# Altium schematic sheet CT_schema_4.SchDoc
size 398 x 262 mm
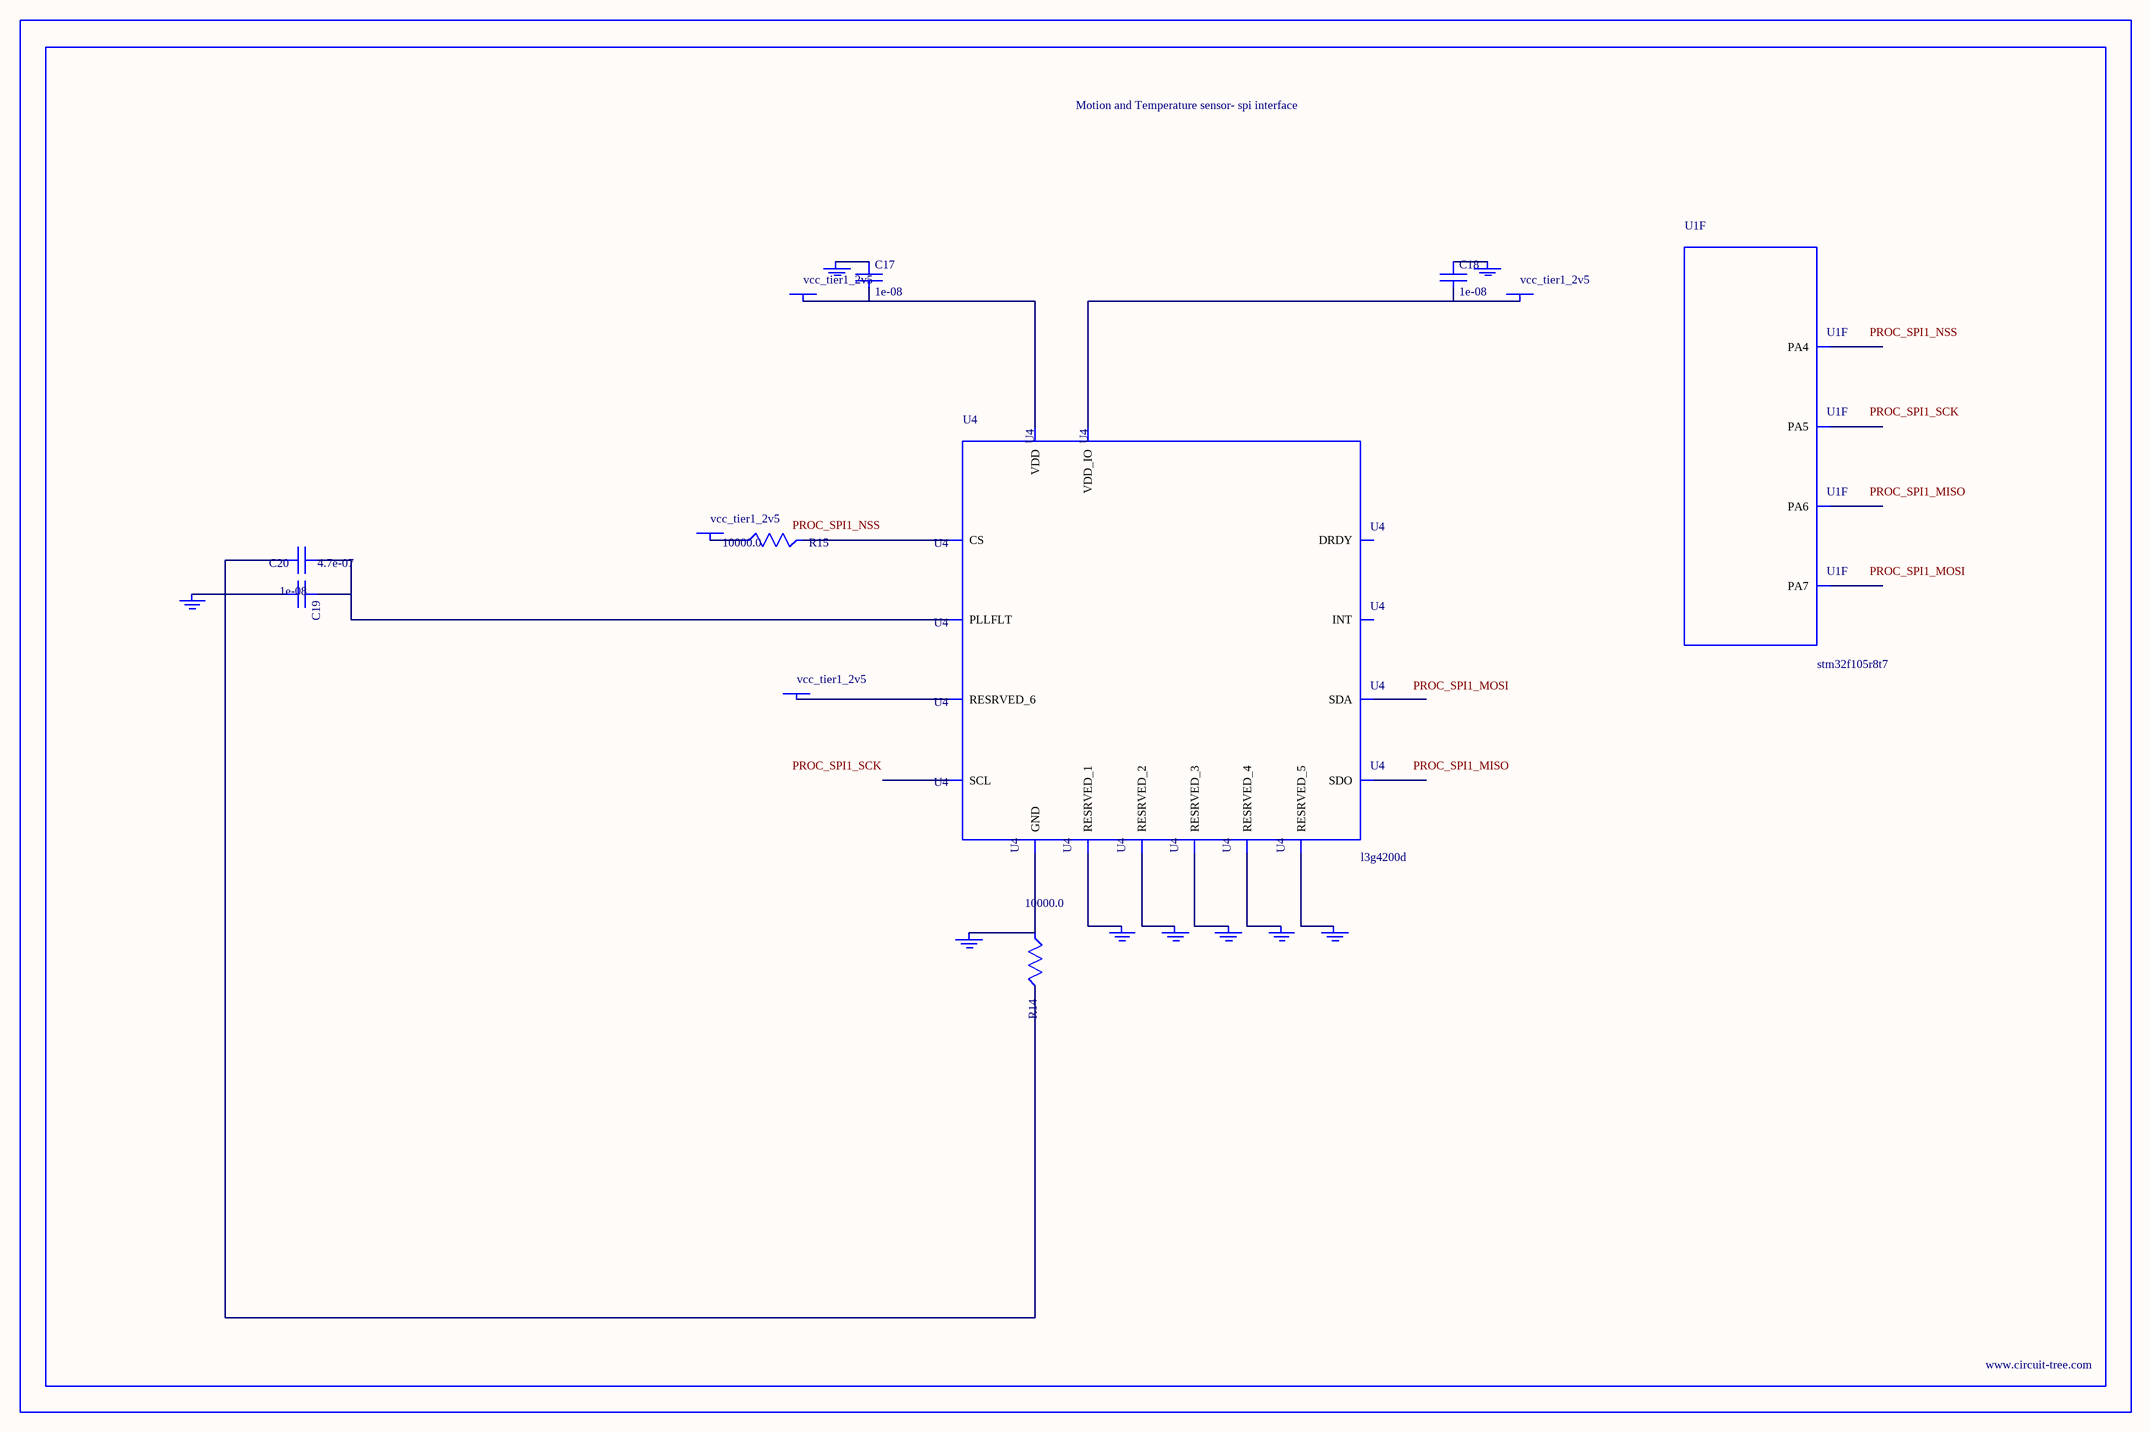
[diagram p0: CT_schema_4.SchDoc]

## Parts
BORDER3  (no value)
C17  1e-08  [C0402]
C18  1e-08  [C0402]
C19  1e-08  [C0402]
C20  4.7e-07  [C0603]
GND_INSTANCE_3_0  (no value)
GND_INSTANCE_3_1  (no value)
GND_INSTANCE_3_2  (no value)
GND_INSTANCE_3_3  (no value)
GND_INSTANCE_3_4  (no value)
GND_INSTANCE_3_5  (no value)
GND_INSTANCE_3_6  (no value)
GND_INSTANCE_3_7  (no value)
GND_INSTANCE_3_8  (no value)
POWER_INSTANCE_3_0  vcc_tier1_2v5
POWER_INSTANCE_3_1  vcc_tier1_2v5
POWER_INSTANCE_3_2  vcc_tier1_2v5
POWER_INSTANCE_3_3  vcc_tier1_2v5
R14  10000.0  [R0603]
R15  10000.0  [R0603]
U1  stm32f105r8t7  [LQFP64]  (part F of 7)
U4  l3g4200d  [LGA-16]

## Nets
NetC17_1: C17.1 GND_INSTANCE_3_8.0(GND)
NetC17_2: C17.2 POWER_INSTANCE_3_3.0(PWR) U4.16(VDD)
NetC18_1: C18.1 GND_INSTANCE_3_0.0(GND)
NetC18_2: C18.2 POWER_INSTANCE_3_0.0(PWR) U4.1(VDD_IO)
NetC19_1: C19.1 C20.1 U4.14(PLLFLT)
NetC19_2: C19.2 C20.2 GND_INSTANCE_3_7.0(GND) R14.2
NetGND_INSTANCE_3_1_0: GND_INSTANCE_3_1.0(GND) U4.8(RESRVED_1)
NetGND_INSTANCE_3_2_0: GND_INSTANCE_3_2.0(GND) U4.9(RESRVED_2)
NetGND_INSTANCE_3_3_0: GND_INSTANCE_3_3.0(GND) U4.10(RESRVED_3)
NetGND_INSTANCE_3_4_0: GND_INSTANCE_3_4.0(GND) U4.11(RESRVED_4)
NetGND_INSTANCE_3_5_0: GND_INSTANCE_3_5.0(GND) U4.12(RESRVED_5)
NetGND_INSTANCE_3_6_0: GND_INSTANCE_3_6.0(GND) R14.1 U4.13(GND)
NetPOWER_INSTANCE_3_1_0: POWER_INSTANCE_3_1.0(PWR) R15.1
NetPOWER_INSTANCE_3_2_0: POWER_INSTANCE_3_2.0(PWR) U4.15(RESRVED_6)
NetR15_2: R15.2 U4.5(CS)

Not connected (* = marked no-connect by the designer): U1 20(PA4) 21(PA5) 22(PA6) 23(PA7); U4 2(SCL) 3(SDA) 4(SDO) 6(DRDY) 7(INT)

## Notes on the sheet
- Labels drawn without touching a wire or pin: PROC_SPI1_MISO, PROC_SPI1_MOSI, PROC_SPI1_NSS, PROC_SPI1_SCK

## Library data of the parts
BORDER3 = BORDER_PAGE3
C17-C19 = C0402C103K3RAC
C20 = C0603C474K3RAC
GND_INSTANCE_3_0-GND_INSTANCE_3_8 = GND
POWER_INSTANCE_3_0-POWER_INSTANCE_3_3 = PWR
R14 R15 = RC0603JR-0710KL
